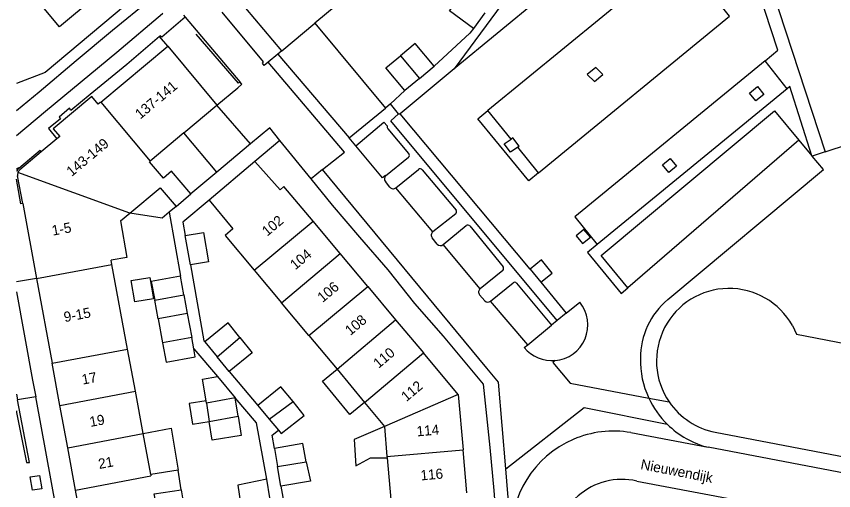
# Model space of a CAD drawing. Extents: x 194485 to 197793, y 468269 to 470822.
# Drawn here: x 194485.4 to 194582.3, y 469286.4 to 469342.6 of the extents above; entities that cross this region are included whole.
import ezdxf

# ---------------------------------------------------------------- set-up
doc = ezdxf.new("R2010")
doc.units = 0
for name, color, linetype in [('BGT grensvlak gebouwinstallatie plus 1', 7, 'Continuous'), ('BGT grensvlak overig bouwwerk uitbreiding populatie', 7, 'Continuous'), ('BGT grensvlak pand op maaiveld', 7, 'Continuous'), ('BGT grensvlak pand op maaiveld LR', 7, 'Continuous'), ('BGT grensvlak scheiding', 7, 'Continuous'), ('BGT grensvlak vegetatieobject', 7, 'Continuous'), ('BGT grensvlak wegdeel', 7, 'Continuous'), ('BGT lijnelement scheiding muur', 7, 'Continuous'), ('BGT tekst huisnummerreeks', 7, 'Continuous'), ('BGT tekst openbare ruimte label weg', 7, 'Continuous')]:
    doc.layers.add(name, color=color, linetype=linetype)

msp = doc.modelspace()

# ---------------------------------------------------------------- linework, layer by layer
at = {"layer": 'BGT grensvlak gebouwinstallatie plus 1'}
for p, q in [((194505.671, 469307.422), (194506.198, 469304.56)), ((194502.209, 469306.785), (194502.736, 469303.924)), ((194521.674, 469299.407), (194523.413, 469300.835)), ((194507.481, 469299.626), (194509.231, 469299.941)), ((194507.889, 469297.052), (194507.481, 469299.626)), ((194509.231, 469299.941), (194511.348, 469297.436)), ((194524.944, 469295.425), (194521.674, 469299.407)), ((194507.929, 469296.797), (194507.889, 469297.052)), ((194526.683, 469296.853), (194524.944, 469295.425)), ((194500.436, 469293.19), (194503.752, 469293.81)), ((194503.752, 469293.81), (194504.586, 469288.828)), ((194504.951, 469286.527), (194505.421, 469283.73))]:
    msp.add_line(p, q, dxfattribs=at)
for points in [[(194507.889, 469297.052), (194505.904, 469296.738), (194506.289, 469294.303), (194508.274, 469294.617)], [(194529.021, 469294.006), (194525.436, 469292.477), (194525.651, 469289.364), (194527.363, 469290.312), (194529.338, 469290.321)]]:
    msp.add_lwpolyline(points, dxfattribs=at)
at = {"layer": 'BGT grensvlak overig bouwwerk uitbreiding populatie'}
for p, q in [((194499.018, 469311.324), (194501.226, 469311.691)), ((194499.441, 469308.779), (194499.018, 469311.324)), ((194501.226, 469311.691), (194501.649, 469309.146)), ((194501.649, 469309.146), (194499.441, 469308.779))]:
    msp.add_line(p, q, dxfattribs=at)
at = {"layer": 'BGT grensvlak pand op maaiveld'}
for p, q in [((194516.86, 469338.535), (194511.011, 469345.533)), ((194524.832, 469345.212), (194520.777, 469341.816)), ((194540.915, 469343.044), (194539.57, 469341.215)), ((194516.86, 469338.535), (194520.777, 469341.816)), ((194495.42, 469332.476), (194503.347, 469339.116)), ((194503.347, 469339.116), (194509.186, 469332.095)), ((194533.174, 469335.279), (194534.908, 469336.728)), ((194533.174, 469335.279), (194531.439, 469333.83)), ((194495.358, 469332.424), (194495.113, 469332.219)), ((194495.358, 469332.424), (194495.42, 469332.476)), ((194505.271, 469328.818), (194509.186, 469332.095)), ((194490.547, 469328.395), (194490.202, 469328.106)), ((194505.271, 469328.818), (194501.278, 469325.478)), ((194490.202, 469328.106), (194488.365, 469326.567)), ((194581.242, 469326.559), (194584.025, 469327.468)), ((194488.365, 469326.567), (194485.839, 469324.451)), ((194513.676, 469325.451), (194508.265, 469320.852)), ((194486.162, 469320.459), (194485.563, 469323.713)), ((194504.335, 469320.105), (194506.091, 469321.605)), ((194486.162, 469320.459), (194487.797, 469311.581)), ((194504.335, 469320.105), (194503.521, 469319.41)), ((194497.77, 469318.408), (194498.847, 469319.299)), ((194523.79, 469314.516), (194520.589, 469318.341)), ((194506.047, 469313.175), (194505.434, 469316.644)), ((194496.745, 469313.229), (194496.649, 469313.749)), ((194527.067, 469310.602), (194523.79, 469314.516)), ((194498.593, 469303.194), (194496.745, 469313.229)), ((194505.264, 469309.637), (194504.856, 469311.852)), ((194513.592, 469312.558), (194516.835, 469308.686)), ((194487.797, 469311.581), (194489.65, 469301.52)), ((194527.067, 469310.602), (194530.35, 469306.679)), ((194502.209, 469306.785), (194501.802, 469309)), ((194505.264, 469309.637), (194505.671, 469307.422)), ((194520.081, 469304.811), (194516.835, 469308.686)), ((194505.671, 469307.422), (194502.209, 469306.785)), ((194530.35, 469306.679), (194533.652, 469302.735)), ((194506.198, 469304.56), (194502.736, 469303.924)), ((194506.44, 469303.245), (194506.198, 469304.56)), ((194507.73, 469304.07), (194509.198, 469302.286)), ((194520.081, 469304.811), (194523.413, 469300.835)), ((194499.515, 469298.192), (194498.593, 469303.194)), ((194510.621, 469300.555), (194509.198, 469302.286)), ((194537.758, 469297.83), (194533.652, 469302.735)), ((194490.576, 469296.495), (194489.65, 469301.52)), ((194523.413, 469300.835), (194526.683, 469296.853)), ((194500.436, 469293.19), (194499.515, 469298.192)), ((194511.348, 469297.436), (194507.929, 469296.797)), ((194511.691, 469295.24), (194511.348, 469297.436)), ((194537.758, 469297.83), (194538.347, 469291.24)), ((194491.498, 469291.489), (194490.576, 469296.495)), ((194507.929, 469296.797), (194508.274, 469294.617)), ((194514.036, 469296.513), (194515.371, 469294.894)), ((194526.683, 469296.853), (194529.021, 469294.006)), ((194515.371, 469294.894), (194516.454, 469293.582)), ((194529.021, 469294.006), (194529.327, 469290.446)), ((194568.222, 469293.348), (194596.632, 469287.931)), ((194501.334, 469288.311), (194500.436, 469293.19)), ((194492.42, 469286.481), (194491.498, 469291.489)), ((194516.008, 469291.424), (194516.372, 469289.282)), ((194529.327, 469290.446), (194529.338, 469290.321)), ((194538.803, 469286.143), (194538.347, 469291.24)), ((194529.338, 469290.321), (194529.766, 469285.355)), ((194504.586, 469288.828), (194501.334, 469288.311)), ((194504.951, 469286.527), (194504.586, 469288.828)), ((194516.768, 469286.953), (194516.372, 469289.282)), ((194515.466, 469285.579), (194515.081, 469287.76)), ((194493.343, 469281.472), (194492.42, 469286.481))]:
    msp.add_line(p, q, dxfattribs=at)
for points in [[(194562.699, 469370.05), (194574.391, 469347.159), (194577.08, 469348.546), (194577.858, 469346.711), (194574.972, 469345.792), (194581.242, 469326.559)], [(194539.57, 469341.215), (194536.753, 469343.292), (194538.097, 469345.119)], [(194534.908, 469336.728), (194532.657, 469339.422), (194530.923, 469337.973)], [(194531.439, 469333.83), (194529.189, 469336.523), (194530.923, 469337.973)], [(194495.113, 469332.219), (194494.343, 469333.139), (194489.777, 469329.315), (194490.547, 469328.395)], [(194577.367, 469305.994), (194577.846, 469304.962), (194585.017, 469303.583), (194587.513, 469306.019), (194584.025, 469327.468)], [(194506.091, 469321.605), (194503.812, 469324.273), (194502.854, 469323.455), (194501.189, 469325.403), (194501.278, 469325.478)], [(194520.589, 469318.341), (194517.12, 469322.485), (194516.655, 469322.061), (194513.676, 469325.451)], [(194508.265, 469320.852), (194511.069, 469317.45), (194510.14, 469316.677), (194513.592, 469312.558)], [(194503.521, 469319.41), (194502.685, 469318.696), (194498.847, 469319.299)], [(194497.77, 469318.408), (194498.488, 469314.045), (194496.649, 469313.749)], [(194505.434, 469316.644), (194507.588, 469317.024), (194508.165, 469313.524), (194506.047, 469313.175)], [(194504.856, 469311.852), (194501.394, 469311.215), (194501.802, 469309)], [(194511.909, 469304.558), (194510.516, 469306.313), (194507.73, 469304.07)], [(194511.909, 469304.558), (194513.345, 469302.748), (194510.621, 469300.555)], [(194502.736, 469303.924), (194503.154, 469301.649), (194506.616, 469302.285), (194506.44, 469303.245)], [(194518.2, 469296.985), (194516.76, 469298.706), (194514.036, 469296.513)], [(194516.454, 469293.582), (194516.79, 469293.174), (194519.513, 469295.304), (194518.2, 469296.985)], [(194511.691, 469295.24), (194512.046, 469292.965), (194508.627, 469292.389), (194508.274, 469294.617)], [(194519.769, 469289.846), (194519.339, 469291.988), (194516.008, 469291.424)], [(194519.769, 469289.846), (194520.262, 469287.529), (194516.768, 469286.953)], [(194515.081, 469287.76), (194511.637, 469287.084), (194511.977, 469284.946)], [(194502.278, 469283.186), (194501.756, 469286.019), (194504.951, 469286.527)]]:
    msp.add_lwpolyline(points, dxfattribs=at)
for centre, radius, start, end in [((194486.351, 469323.84), 0.797, 129.96909, 159.60924), ((194486.344, 469323.838), 0.792, 159.31836, 189.1204), ((194569.865, 469301.789), 8.6, 29.26809, 214.38075), ((194569.865, 469301.79), 8.601, 214.38599, 258.98856)]:
    msp.add_arc(centre, radius, start, end, dxfattribs=at)
at = {"layer": 'BGT grensvlak pand op maaiveld LR'}
for p, q in [((194530.923, 469337.973), (194533.174, 469335.279)), ((194495.42, 469332.476), (194501.278, 469325.478)), ((194498.847, 469319.299), (194485.604, 469324.118)), ((194513.592, 469312.558), (194520.589, 469318.341)), ((194516.835, 469308.686), (194523.79, 469314.516)), ((194487.797, 469311.581), (194496.745, 469313.229)), ((194520.081, 469304.811), (194527.067, 469310.602)), ((194501.802, 469309), (194505.264, 469309.637)), ((194523.413, 469300.835), (194530.35, 469306.679)), ((194509.198, 469302.286), (194511.909, 469304.558)), ((194489.65, 469301.52), (194498.593, 469303.194)), ((194526.683, 469296.853), (194533.652, 469302.735)), ((194490.576, 469296.495), (194499.515, 469298.192)), ((194537.758, 469297.83), (194529.021, 469294.006)), ((194515.371, 469294.894), (194518.2, 469296.985)), ((194508.274, 469294.617), (194511.691, 469295.24)), ((194491.498, 469291.489), (194500.436, 469293.19)), ((194529.327, 469290.446), (194538.347, 469291.24)), ((194516.372, 469289.282), (194519.769, 469289.846)), ((194492.42, 469286.481), (194501.357, 469288.188)), ((194501.334, 469288.311), (194501.357, 469288.188))]:
    msp.add_line(p, q, dxfattribs=at)
msp.add_lwpolyline([(194498.847, 469319.299), (194502.464, 469322.295), (194504.335, 469320.105)], dxfattribs=at)
at = {"layer": 'BGT grensvlak scheiding'}
for p, q in [((194485.411, 469297.862), (194485.545, 469297.192)), ((194485.411, 469295.858), (194485.445, 469295.687))]:
    msp.add_line(p, q, dxfattribs=at)
msp.add_lwpolyline([(194485.445, 469295.687), (194486.618, 469289.756), (194486.956, 469289.769), (194485.545, 469297.192)], dxfattribs=at)
at = {"layer": 'BGT grensvlak vegetatieobject'}
msp.add_line((194546.289, 469312.657), (194547.547, 469311.119), dxfattribs=at)
at = {"layer": 'BGT grensvlak wegdeel'}
for p, q in [((194552.139, 469356.588), (194537.301, 469336.406)), ((194547.495, 469344.838), (194537.301, 469336.406)), ((194505.226, 469342.762), (194505.424, 469342.527)), ((194505.424, 469342.527), (194511.882, 469334.869)), ((194520.777, 469341.816), (194529.146, 469331.771)), ((194503.347, 469339.116), (194502.39, 469340.266)), ((194516.409, 469338.157), (194524.839, 469328.237)), ((194576.746, 469334.039), (194574.12, 469337.347)), ((194537.301, 469336.406), (194530.884, 469331.098)), ((194576.746, 469334.039), (194554.246, 469315.592)), ((194531.439, 469333.83), (194529.734, 469332.254)), ((194513.159, 469327.522), (194509.186, 469332.095)), ((194529.734, 469332.254), (194529.146, 469331.771)), ((194530.704, 469331.075), (194529.734, 469332.254)), ((194524.839, 469328.237), (194529.146, 469331.771)), ((194530.704, 469331.075), (194530.884, 469331.098)), ((194546.289, 469312.657), (194530.884, 469331.098)), ((194544.028, 469328.082), (194541.264, 469331.458)), ((194515.438, 469329.432), (194513.159, 469327.522)), ((194516.649, 469327.936), (194515.438, 469329.432)), ((194531.917, 469326.377), (194529.453, 469329.316)), ((194509.173, 469324.181), (194505.271, 469328.818)), ((194525.626, 469327.292), (194524.839, 469328.237)), ((194513.159, 469327.522), (194509.173, 469324.181)), ((194516.649, 469327.936), (194513.676, 469325.451)), ((194520.352, 469323.361), (194516.649, 469327.936)), ((194578.141, 469327.95), (194557.877, 469310.444)), ((194578.141, 469327.95), (194579.687, 469326.104)), ((194547.281, 469324.107), (194544.813, 469327.123)), ((194581.242, 469326.559), (194579.722, 469326.062)), ((194529.17, 469323.725), (194531.878, 469325.952)), ((194579.722, 469326.062), (194579.687, 469326.104)), ((194485.652, 469324.675), (194485.411, 469324.472)), ((194485.698, 469324.62), (194485.652, 469324.675)), ((194521.687, 469324.495), (194520.352, 469323.361)), ((194541.164, 469300.931), (194521.687, 469324.495)), ((194530.375, 469322.318), (194533.077, 469324.502)), ((194533.496, 469324.461), (194537.512, 469319.647)), ((194509.173, 469324.181), (194506.091, 469321.605)), ((194529.672, 469322.392), (194529.134, 469323.055)), ((194534.762, 469317.093), (194530.375, 469322.318)), ((194503.521, 469319.41), (194504.856, 469311.852)), ((194537.467, 469319.219), (194534.762, 469317.093)), ((194535.993, 469315.585), (194538.729, 469317.832)), ((194539.152, 469317.789), (194543.084, 469312.948)), ((194535.291, 469315.652), (194534.686, 469316.381)), ((194540.366, 469310.348), (194535.993, 469315.585)), ((194543.04, 469312.526), (194540.366, 469310.348)), ((194487.797, 469311.581), (194485.411, 469311.154)), ((194541.601, 469308.872), (194544.268, 469311.048)), ((194544.688, 469311.008), (194548.837, 469306.023)), ((194547.547, 469311.119), (194550.562, 469307.435)), ((194540.906, 469308.933), (194540.303, 469309.634)), ((194545.997, 469303.699), (194541.601, 469308.872)), ((194506.44, 469303.245), (194509.231, 469299.941)), ((194510.621, 469300.555), (194514.036, 469296.513)), ((194487.702, 469297.528), (194485.545, 469297.192)), ((194494.46, 469260.741), (194487.702, 469297.528)), ((194560.343, 469297.394), (194562.767, 469296.933)), ((194485.411, 469295.681), (194485.445, 469295.687)), ((194558.209, 469293.295), (194567.394, 469291.55)), ((194596.61, 469285.957), (194567.394, 469291.55)), ((194544.1, 469280.669), (194543.399, 469289.021)), ((194558.927, 469287.558), (194573.627, 469284.754)), ((194516.768, 469286.953), (194518.645, 469276.521))]:
    msp.add_line(p, q, dxfattribs=at)
for points in [[(194488.3, 469344.04), (194508.91, 469361.26), (194511.2, 469358.63), (194490.54, 469341.38), (194488.3, 469344.04)], [(194574.12, 469337.347), (194575.622, 469338.634), (194573.337, 469345.676), (194565.604, 469360.695), (194562.476, 469358.04)], [(194547.281, 469324.107), (194569.906, 469342.655), (194563.999, 469350.097), (194541.264, 469331.458)], [(194501.029, 469346.251), (194488.84, 469335.99), (194485.411, 469334.682)], [(194501.737, 469345.056), (194501.251, 469344.647), (194496.823, 469340.973), (194492.496, 469337.372), (194488.129, 469333.669), (194485.411, 469331.436)], [(194485.411, 469328.507), (194488.855, 469331.398), (194497.299, 469338.391), (194502.723, 469342.962), (194502.787, 469343.015)], [(194505.424, 469342.527), (194502.633, 469340.183), (194502.443, 469340.311), (194502.39, 469340.266)], [(194539.57, 469341.215), (194539.162, 469340.66), (194534.908, 469336.728)], [(194502.39, 469340.266), (194498.512, 469336.949), (194494.152, 469333.381), (194491.879, 469331.471), (194491.718, 469331.735), (194490.475, 469330.704), (194490.637, 469330.48), (194489.24, 469329.326), (194490.202, 469328.106)], [(194521.687, 469324.495), (194524.308, 469326.527), (194515.254, 469337.19)], [(194574.12, 469337.347), (194551.571, 469318.86), (194554.246, 469315.592)], [(194553.058, 469335.754), (194553.897, 469334.916), (194554.911, 469335.744), (194554.067, 469336.585), (194553.058, 469335.754)], [(194572.294, 469333.549), (194573.213, 469334.304), (194573.971, 469333.387), (194573.036, 469332.634), (194572.294, 469333.549)], [(194579.687, 469326.104), (194577.072, 469334.31), (194576.746, 469334.039)], [(194547.281, 469324.107), (194546.121, 469323.156), (194540.104, 469330.507), (194541.264, 469331.458)], [(194557.877, 469310.444), (194554.725, 469314.273), (194575.235, 469331.419), (194578.141, 469327.95)], [(194549.5, 469306.566), (194529.791, 469330.265), (194530.704, 469331.075)], [(194525.626, 469327.292), (194528.972, 469330.088), (194529.337, 469329.649)], [(194544.813, 469327.123), (194544.971, 469327.234), (194544.235, 469328.22), (194544.028, 469328.082)], [(194529.17, 469323.725), (194529.141, 469323.754), (194528.803, 469323.477), (194525.626, 469327.292)], [(194544.813, 469327.123), (194543.972, 469326.532), (194543.196, 469327.529), (194544.028, 469328.082)], [(194488.365, 469326.567), (194488.224, 469326.736), (194485.698, 469324.62)], [(194562.716, 469324.115), (194561.97, 469325.029), (194562.893, 469325.801), (194563.639, 469324.887), (194562.716, 469324.115)], [(194562.587, 469309.068), (194581.04, 469324.488), (194579.722, 469326.062)], [(194543.77, 469265.431), (194543.677, 469265.893), (194543.245, 469271.189), (194542.901, 469276.322), (194542.418, 469281.342), (194542.035, 469286.425), (194541.54, 469291.521), (194540.766, 469299.033), (194536.018, 469304.732), (194532.615, 469308.587), (194529.45, 469312.578), (194526.122, 469316.47), (194522.882, 469320.236), (194520.352, 469323.361)], [(194486.162, 469320.459), (194485.946, 469320.419), (194485.411, 469323.32)], [(194508.265, 469320.852), (194505.15, 469318.249), (194505.434, 469316.644)], [(194551.735, 469316.62), (194552.49, 469315.712), (194553.446, 469316.455), (194552.643, 469317.371), (194551.735, 469316.62)], [(194554.246, 469315.592), (194553.089, 469314.644), (194557.077, 469309.772), (194557.877, 469310.444)], [(194547.547, 469311.119), (194548.904, 469312.202), (194547.62, 469313.791), (194546.289, 469312.657)], [(194506.047, 469313.175), (194507.636, 469304.181), (194507.73, 469304.07)], [(194485.411, 469310), (194487.34, 469299.498), (194487.702, 469297.528)], [(194549.251, 469301.838), (194548.986, 469301.617), (194551.036, 469299.166), (194560.343, 469297.394)], [(194543.399, 469289.021), (194542.537, 469299.292), (194541.164, 469300.931)], [(194515.081, 469287.76), (194513.875, 469294.445), (194511.348, 469297.436)], [(194543.399, 469289.021), (194552.676, 469296.283), (194562.542, 469294.282)], [(194516.008, 469291.424), (194515.728, 469292.983), (194516.454, 469293.582)], [(194487.043, 469288.042), (194488.144, 469288.216), (194488.418, 469286.64), (194487.329, 469286.453), (194487.043, 469288.042)]]:
    msp.add_lwpolyline(points, dxfattribs=at)
for centre, radius, start, end in [((194529.837, 469329.636), 0.5, 178.55987, 219.85153), ((194531.687, 469326.184), 0.301, 309.52042, 39.99349), ((194486.356, 469323.837), 1.023, 130.00928, 157.4143), ((194533.266, 469324.268), 0.301, 40.00302, 128.81954), ((194529.522, 469323.37), 0.5, 134.80242, 219.04633), ((194530.06, 469322.705), 0.499, 218.87483, 309.10716), ((194537.282, 469319.455), 0.3, 308.12816, 39.86777), ((194538.919, 469317.602), 0.299, 38.80565, 129.58544), ((194535.071, 469316.7), 0.5, 128.21147, 219.60299), ((194535.676, 469315.972), 0.501, 219.79053, 309.30569), ((194542.85, 469312.759), 0.301, 309.23605, 38.85903), ((194544.458, 469310.815), 0.301, 40.02751, 129.09183), ((194540.679, 469309.961), 0.498, 128.97647, 220.93863), ((194541.285, 469309.258), 0.499, 220.67029, 309.29774), ((194568.454, 469302.104), 9.106, 130.11274, 180.10088), ((194570.051, 469301.904), 10.704, 179.0165, 204.91948), ((194570.026, 469301.903), 10.681, 204.97071, 225.52084), ((194556.161, 469281.379), 12.091, 80.24549, 113.17711), ((194570.029, 469301.905), 10.685, 225.51341, 255.72176), ((194556.157, 469281.391), 12.079, 113.18352, 183.42538), ((194557.188, 469279.826), 7.925, 77.32516, 185.02142)]:
    msp.add_arc(centre, radius, start, end, dxfattribs=at)
at = {"layer": 'BGT lijnelement scheiding muur'}
for p, q in [((194516.409, 469338.157), (194515.254, 469337.19)), ((194516.86, 469338.535), (194516.409, 469338.157)), ((194550.562, 469307.435), (194552.172, 469308.753)), ((194550.562, 469307.435), (194549.5, 469306.566)), ((194545.997, 469303.699), (194548.837, 469306.023)), ((194549.5, 469306.566), (194548.837, 469306.023)), ((194545.596, 469303.371), (194545.997, 469303.699))]:
    msp.add_line(p, q, dxfattribs=at)
for points in [[(194515.254, 469337.19), (194514.782, 469336.795), (194514.568, 469337.087), (194514.682, 469337.237), (194509.796, 469343.137)], [(194511.882, 469334.869), (194511.719, 469334.72), (194506.733, 469340.545)], [(194509.186, 469332.095), (194511.639, 469334.17), (194512.129, 469334.584), (194511.882, 469334.869)]]:
    msp.add_lwpolyline(points, dxfattribs=at)
for centre, radius, start, end in [((194548.877, 469306.07), 4.249, 275.04447, 39.15567), ((194548.877, 469306.069), 4.248, 219.43755, 275.05362)]:
    msp.add_arc(centre, radius, start, end, dxfattribs=at)

# ---------------------------------------------------------------- texts
at = {"layer": 'BGT tekst huisnummerreeks'}
for s, rotation, p in [('137-141', 40, (194500.1, 469330.393)), ('143-149', 39.9, (194491.967, 469323.587)), ('102', 39.9, (194515.133, 469316.516)), ('1-5', 10.4, (194489.735, 469316.641)), ('104', 39.9, (194518.466, 469312.53)), ('106', 39.9, (194521.703, 469308.658)), ('9-15', 10.4, (194491.149, 469306.388)), ('108', 39.9, (194524.982, 469304.74)), ('110', 39.9, (194528.325, 469300.848)), ('17', 10.4, (194493.276, 469298.98)), ('112', 39.9, (194531.629, 469296.907)), ('19', 10.4, (194494.199, 469293.965)), ('114', 5.1, (194532.887, 469292.841)), ('21', 10.4, (194495.236, 469288.978)), ('116', 5.1, (194533.352, 469287.622))]:
    msp.add_text(s, height=1.2, rotation=rotation, dxfattribs=at).set_placement(p)
at = {"layer": 'BGT tekst openbare ruimte label weg'}
msp.add_text('Nieuwendijk', height=1.2, rotation=349, dxfattribs=at).set_placement((194559.308, 469288.98))

doc.saveas('drawing.dxf')
